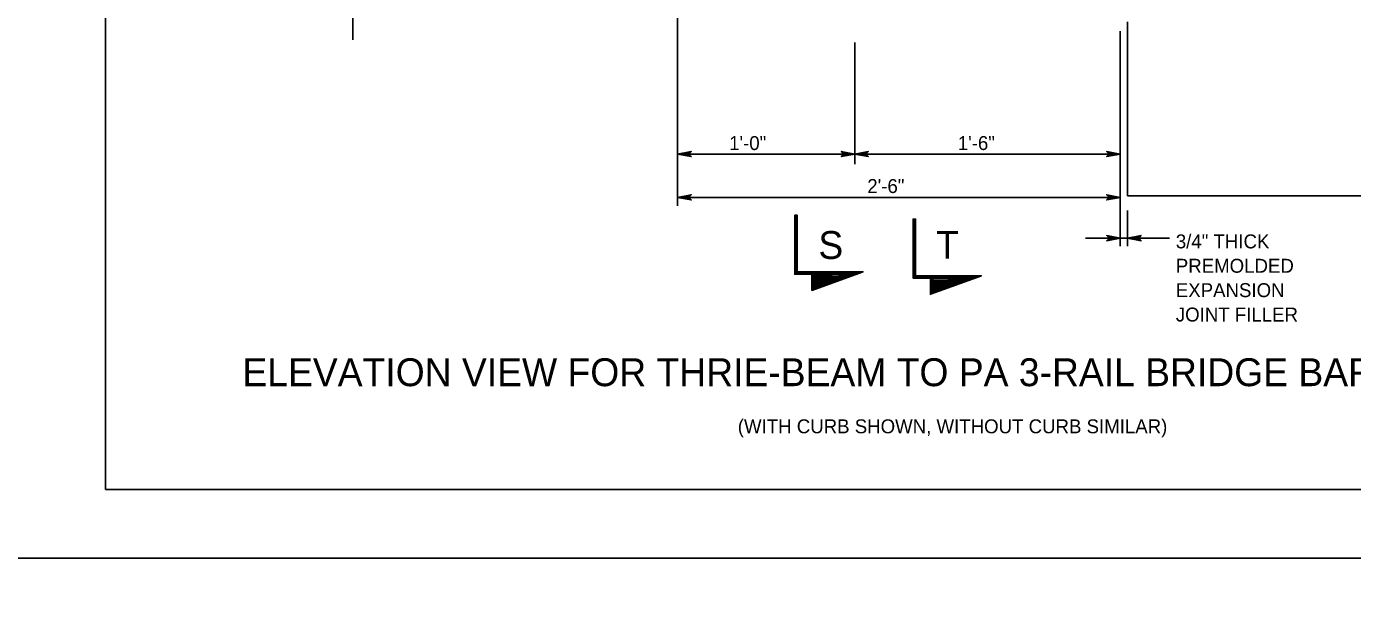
# Model space of a CAD drawing. Extents: x 632007860 to 635435983, y 295418622 to 297794622.
# Drawn here: x 634553598 to 634843672, y 296599122 to 296722900 of the extents above; entities that cross this region are included whole.
import ezdxf

# ---------------------------------------------------------------- set-up
doc = ezdxf.new("R2010")
doc.units = 0
for name, color, linetype in [('1', 7, 'Continuous'), ('PLT-BNDY', 7, 'Continuous'), ('S-DETL-DIMS', 7, 'Continuous'), ('S-DETL-T120', 7, 'Continuous'), ('S-DETL-T240', 7, 'Continuous'), ('S-STEL', 7, 'Continuous')]:
    doc.layers.add(name, color=color, linetype=linetype)

msp = doc.modelspace()

# ---------------------------------------------------------------- linework, layer by layer
at = {"layer": '1'}
for p, q in [((634570860, 296621622), (634570860, 297185622)), ((635356860, 296621622), (634570860, 296621622))]:
    msp.add_line(p, q, dxfattribs=at)
at = {"layer": 'PLT-BNDY'}
for points in [[(634530860, 297200622), (635371860, 297200622), (635371860, 296606622), (634530860, 296606622)], [(634530860, 296606622), (635371860, 296606622), (635371860, 296012622), (634530860, 296012622)]]:
    msp.add_lwpolyline(points, close=True, dxfattribs=at)
at = {"layer": 'S-DETL-DIMS'}
for p, q in [((634696041, 296683686), (634696041, 296743199)), ((634624952, 296729210), (634624952, 296720021)), ((634792877, 296674845), (634792877, 296721892)), ((634734775, 296692766), (634734775, 296719419)), ((634696041, 296694999), (634792877, 296694999)), ((634696041, 296685540), (634792877, 296685540)), ((634794471, 296682637), (634794471, 296674845)), ((634803645, 296676612), (634785302, 296676612))]:
    msp.add_line(p, q, dxfattribs=at)
for points in [[(634696041, 296694999), (634699001, 296694444), (634698887, 296694523), (634698773, 296694602), (634698714, 296694701), (634698655, 296694801), (634698638, 296694900), (634698621, 296694999), (634698638, 296695098), (634698655, 296695197), (634698714, 296695297), (634698773, 296695396), (634698887, 296695475), (634699001, 296695554), (634696041, 296694999), (634698887, 296695475), (634698773, 296695396), (634696041, 296694999), (634698714, 296695297), (634698655, 296695197), (634696041, 296694999), (634698638, 296695098), (634698621, 296694999), (634696041, 296694999), (634698638, 296694900), (634698655, 296694801), (634696041, 296694999), (634698714, 296694701), (634698773, 296694602), (634696041, 296694999), (634698887, 296694523)], [(634734775, 296694999), (634731816, 296695554), (634731930, 296695475), (634732044, 296695396), (634732103, 296695297), (634732162, 296695197), (634732179, 296695098), (634732196, 296694999), (634732179, 296694900), (634732162, 296694801), (634732103, 296694701), (634732044, 296694602), (634731930, 296694523), (634731816, 296694444), (634734775, 296694999), (634731930, 296694523), (634732044, 296694602), (634734775, 296694999), (634732103, 296694701), (634732162, 296694801), (634734775, 296694999), (634732179, 296694900), (634732196, 296694999), (634734775, 296694999), (634732179, 296695098), (634732162, 296695197), (634734775, 296694999), (634732103, 296695297), (634732044, 296695396), (634734775, 296694999), (634731930, 296695475)], [(634734775, 296694999), (634737735, 296694444), (634737621, 296694523), (634737507, 296694602), (634737448, 296694701), (634737389, 296694801), (634737372, 296694900), (634737355, 296694999), (634737372, 296695098), (634737389, 296695197), (634737448, 296695297), (634737507, 296695396), (634737621, 296695475), (634737735, 296695554), (634734775, 296694999), (634737621, 296695475), (634737507, 296695396), (634734775, 296694999), (634737448, 296695297), (634737389, 296695197), (634734775, 296694999), (634737372, 296695098), (634737355, 296694999), (634734775, 296694999), (634737372, 296694900), (634737389, 296694801), (634734775, 296694999), (634737448, 296694701), (634737507, 296694602), (634734775, 296694999), (634737621, 296694523)], [(634792877, 296694999), (634789917, 296695554), (634790031, 296695475), (634790145, 296695396), (634790204, 296695297), (634790263, 296695197), (634790280, 296695098), (634790297, 296694999), (634790280, 296694900), (634790263, 296694801), (634790204, 296694701), (634790145, 296694602), (634790031, 296694523), (634789917, 296694444), (634792877, 296694999), (634790031, 296694523), (634790145, 296694602), (634792877, 296694999), (634790204, 296694701), (634790263, 296694801), (634792877, 296694999), (634790280, 296694900), (634790297, 296694999), (634792877, 296694999), (634790280, 296695098), (634790263, 296695197), (634792877, 296694999), (634790204, 296695297), (634790145, 296695396), (634792877, 296694999), (634790031, 296695475)], [(634696041, 296685540), (634699001, 296684985), (634698887, 296685064), (634698773, 296685143), (634698714, 296685242), (634698655, 296685341), (634698638, 296685440), (634698621, 296685540), (634698638, 296685639), (634698655, 296685738), (634698714, 296685837), (634698773, 296685936), (634698887, 296686015), (634699001, 296686094), (634696041, 296685540), (634698887, 296686015), (634698773, 296685936), (634696041, 296685540), (634698714, 296685837), (634698655, 296685738), (634696041, 296685540), (634698638, 296685639), (634698621, 296685540), (634696041, 296685540), (634698638, 296685440), (634698655, 296685341), (634696041, 296685540), (634698714, 296685242), (634698773, 296685143), (634696041, 296685540), (634698887, 296685064)], [(634792877, 296685540), (634789917, 296686094), (634790031, 296686015), (634790145, 296685936), (634790204, 296685837), (634790263, 296685738), (634790280, 296685639), (634790297, 296685540), (634790280, 296685440), (634790263, 296685341), (634790204, 296685242), (634790145, 296685143), (634790031, 296685064), (634789917, 296684985), (634792877, 296685540), (634790031, 296685064), (634790145, 296685143), (634792877, 296685540), (634790204, 296685242), (634790263, 296685341), (634792877, 296685540), (634790280, 296685440), (634790297, 296685540), (634792877, 296685540), (634790280, 296685639), (634790263, 296685738), (634792877, 296685540), (634790204, 296685837), (634790145, 296685936), (634792877, 296685540), (634790031, 296686015)], [(634721935, 296681635), (634721935, 296668993), (634735855, 296668993), (634736594, 296669262), (634722204, 296669262), (634722204, 296681635), (634721666, 296681635), (634721666, 296668724), (634735116, 296668724), (634725432, 296665199), (634725432, 296668724), (634736594, 296669262), (634725779, 296665632), (634725755, 296668465), (634734022, 296668558), (634726070, 296666005), (634726070, 296668162), (634732366, 296668255), (634726373, 296666389), (634726385, 296667835), (634731270, 296668080), (634726665, 296666798), (634726676, 296667567), (634729825, 296667824), (634726921, 296667066), (634726956, 296667392), (634728670, 296667590), (634726928, 296667227), (634725432, 296665199), (634725432, 296668724), (634726956, 296667392), (634736594, 296669262)], [(634747834, 296680781), (634747834, 296668138), (634761753, 296668138), (634762492, 296668407), (634748103, 296668407), (634748103, 296680781), (634747565, 296680781), (634747565, 296667869), (634761014, 296667869), (634751331, 296664345), (634751331, 296667869), (634762492, 296668407), (634751677, 296664777), (634751654, 296667611), (634759921, 296667704), (634751969, 296665150), (634751969, 296667307), (634758265, 296667401), (634752272, 296665535), (634752284, 296666981), (634757169, 296667226), (634752563, 296665943), (634752575, 296666713), (634755723, 296666969), (634752820, 296666212), (634752855, 296666538), (634754569, 296666736), (634752826, 296666373), (634751331, 296664345), (634751331, 296667869), (634752855, 296666538), (634762492, 296668407)], [(634792877, 296676612), (634789917, 296677166), (634790031, 296677087), (634790145, 296677008), (634790204, 296676909), (634790263, 296676810), (634790280, 296676711), (634790297, 296676612), (634790280, 296676512), (634790263, 296676413), (634790204, 296676314), (634790145, 296676215), (634790031, 296676136), (634789917, 296676057), (634792877, 296676612), (634790031, 296676136), (634790145, 296676215), (634792877, 296676612), (634790204, 296676314), (634790263, 296676413), (634792877, 296676612), (634790280, 296676512), (634790297, 296676612), (634792877, 296676612), (634790280, 296676711), (634790263, 296676810), (634792877, 296676612), (634790204, 296676909), (634790145, 296677008), (634792877, 296676612), (634790031, 296677087)], [(634794471, 296676612), (634797430, 296676057), (634797316, 296676136), (634797202, 296676215), (634797144, 296676314), (634797085, 296676413), (634797068, 296676512), (634797051, 296676612), (634797068, 296676711), (634797085, 296676810), (634797144, 296676909), (634797202, 296677008), (634797316, 296677087), (634797430, 296677166), (634794471, 296676612), (634797316, 296677087), (634797202, 296677008), (634794471, 296676612), (634797144, 296676909), (634797085, 296676810), (634794471, 296676612), (634797068, 296676711), (634797051, 296676612), (634794471, 296676612), (634797068, 296676512), (634797085, 296676413), (634794471, 296676612), (634797144, 296676314), (634797202, 296676215), (634794471, 296676612), (634797316, 296676136)]]:
    msp.add_lwpolyline(points, dxfattribs=at)
for points in [[(634722204, 296681635), (634721666, 296681635), (634721666, 296668724), (634725432, 296668724), (634725432, 296665199), (634736594, 296669262), (634722204, 296669262)], [(634748103, 296680781), (634747565, 296680781), (634747565, 296667869), (634751331, 296667869), (634751331, 296664345), (634762492, 296668407), (634748103, 296668407)]]:
    msp.add_lwpolyline(points, close=True, dxfattribs=at)
at = {"layer": 'S-STEL'}
for p, q in [((634794471, 296723919), (634794471, 296685861)), ((634794471, 296685861), (634930789, 296685861))]:
    msp.add_line(p, q, dxfattribs=at)

# ---------------------------------------------------------------- texts
at = {"layer": 'S-DETL-T120'}
for s, height, p in [('1\'-0"', 3048.1, (634707310, 296695886)), ('1\'-6"', 3048.1, (634757330, 296695886)), ('2\'-6"', 3048.1, (634737534, 296686482)), ('3/4" THICK ', 3048.07, (634805025, 296674384)), ('PREMOLDED ', 3048.1, (634805025, 296669050)), ('EXPANSION ', 3048.1, (634805025, 296663716)), ('JOINT FILLER', 3048.07, (634805025, 296658382)), ('(WITH CURB SHOWN, WITHOUT CURB SIMILAR)', 3048.01, (634709202, 296633935))]:
    msp.add_text(s, height=height, dxfattribs=at).set_placement(p)
at = {"layer": 'S-DETL-T240'}
for s, p in [('S', (634726831, 296672067)), ('T', (634752565, 296672110)), ('ELEVATION VIEW FOR THRIE-BEAM TO PA 3-RAIL BRIDGE BARRIER', (634600834, 296644243))]:
    msp.add_text(s, height=6096, dxfattribs=at).set_placement(p)

doc.saveas('drawing.dxf')
